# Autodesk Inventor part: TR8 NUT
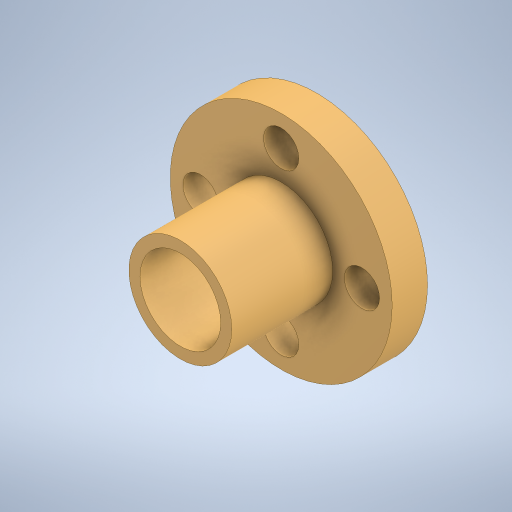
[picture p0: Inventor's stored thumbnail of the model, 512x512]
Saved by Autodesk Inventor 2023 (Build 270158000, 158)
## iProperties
Created: 2025-07
Part Number: TR8 NUT
Material: Generic
Document SubType Name: Modeling
Designer: erjon
Density: 1 g/cm^3
Appearance: Default
Author: erjon
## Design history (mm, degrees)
feature "Base1"
body "Solid1"
